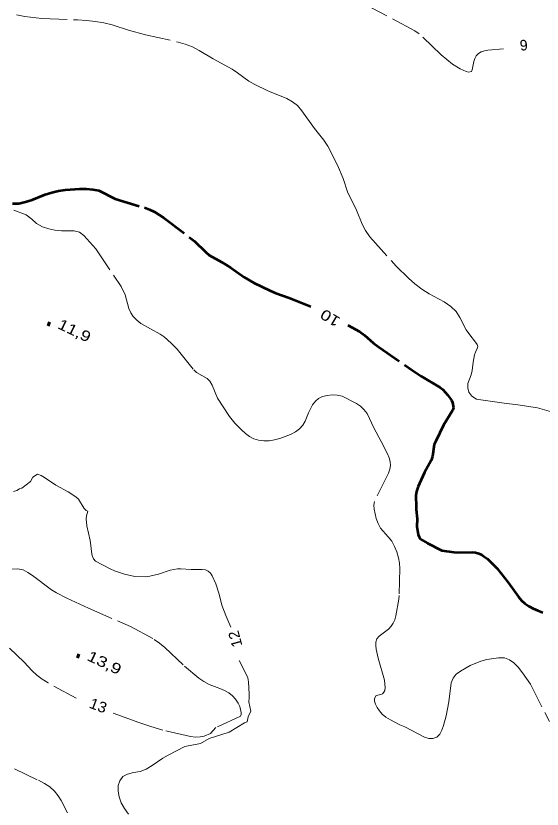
# Model space of a CAD drawing. Extents: x 355726 to 357533, y 5103782 to 5105258.
# Drawn here: x 356617.7 to 356692.4, y 5104170 to 5104282.7 of the extents above; entities that cross this region are included whole.
import ezdxf
from ezdxf.enums import TextEntityAlignment as Align

# ---------------------------------------------------------------- set-up
doc = ezdxf.new("R2010")
doc.units = 0
doc.header["$LTSCALE"] = 0.6
doc.linetypes.add('LONG_DASHED', pattern=[7.5, 6, -1.5])
for name, color, linetype, lineweight in [('1', 7, 'LONG_DASHED', 53), ('2', 7, 'LONG_DASHED', 13), ('3', 7, 'Continuous', 140)]:
    doc.layers.add(name, color=color, linetype=linetype, lineweight=lineweight)

msp = doc.modelspace()

# ---------------------------------------------------------------- linework, layer by layer
at = {"layer": '1'}
for points in [[(356617.23, 5104256.04), (356618.14, 5104256.07), (356619.1, 5104256.28), (356620.05, 5104256.59), (356621.87, 5104257.34), (356622.82, 5104257.63), (356623.78, 5104257.86), (356624.75, 5104258.01), (356626.76, 5104258.13), (356627.76, 5104258.11), (356628.66, 5104258.05), (356629.5, 5104257.88), (356631.8, 5104256.73), (356635.96, 5104255.47), (356636.71, 5104255.2), (356637.42, 5104254.86), (356638.74, 5104254.01), (356643.09, 5104250.7), (356644.67, 5104249.12), (356645.18, 5104248.69), (356646.95, 5104247.73), (356648.19, 5104246.98), (356650.12, 5104245.57), (356651.51, 5104244.8), (356653.76, 5104243.69), (356654.62, 5104243.32), (356656.53, 5104242.67), (356659.58, 5104241.42)], [(356664.84, 5104238.79), (356666.5, 5104237.88), (356667.22, 5104237.34), (356668.52, 5104236.2), (356669.19, 5104235.69), (356673.97, 5104232.38), (356675.27, 5104231.51), (356677.95, 5104229.93), (356678.33, 5104229.61), (356679.03, 5104228.86), (356679.56, 5104228.13), (356679.71, 5104227.79), (356679.84, 5104227.03), (356679.71, 5104226.66), (356678.45, 5104224.58), (356677.33, 5104222.3), (356677.12, 5104221.8), (356676.86, 5104220.13), (356676.67, 5104219.55), (356675.76, 5104217.82), (356675.01, 5104216.26), (356674.82, 5104215.84), (356674.6, 5104215.13), (356674.51, 5104214.51), (356674.58, 5104213.03), (356674.56, 5104212.57), (356674.7, 5104211.26), (356674.65, 5104210.15), (356674.86, 5104209.01), (356674.97, 5104208.68), (356675.17, 5104208.38), (356676.17, 5104207.8), (356678.2, 5104206.76), (356679.9, 5104206.51), (356680.43, 5104206.48), (356682.49, 5104206.51), (356682.98, 5104206.46), (356683.45, 5104206.34), (356683.86, 5104206.12), (356684.28, 5104205.88), (356684.71, 5104205.55), (356686.06, 5104204.19), (356687.64, 5104202.19), (356689.1, 5104200.16), (356689.52, 5104199.66), (356690.01, 5104199.24), (356690.57, 5104198.86), (356691.19, 5104198.53), (356691.84, 5104198.21), (356692.56, 5104197.94)]]:
    msp.add_lwpolyline(points, dxfattribs=at)
at = {"layer": '2'}
for points in [[(356686.94, 5104278), (356684.75, 5104277.84), (356684.27, 5104277.76), (356683.8, 5104277.59), (356683.4, 5104277.34), (356683.09, 5104277.04), (356682.88, 5104276.63), (356682.73, 5104276.23), (356682.53, 5104275.03), (356682.41, 5104274.8), (356682, 5104274.71), (356681.68, 5104274.8), (356680.81, 5104275.19), (356679.73, 5104275.82), (356678.12, 5104277.19), (356674.98, 5104280.15), (356674.36, 5104280.58), (356664.65, 5104285.73)], [(356617.82, 5104282.87), (356619, 5104282.62), (356621.38, 5104282.32), (356626.46, 5104282.13), (356627.75, 5104282.04), (356629, 5104281.9), (356630.22, 5104281.7), (356631.4, 5104281.42), (356633.72, 5104280.69), (356636.11, 5104280.01), (356640.75, 5104278.98), (356641.77, 5104278.68), (356642.78, 5104278.3), (356643.74, 5104277.8), (356645.72, 5104276.59), (356648.44, 5104275.12), (356649.21, 5104274.62), (356650.78, 5104273.44), (356651.63, 5104272.97), (356653.5, 5104272.07), (356656.19, 5104270.96), (356656.98, 5104270.51), (356657.7, 5104269.95), (356658.32, 5104269.23), (356660.14, 5104266.69), (356661.45, 5104265.07), (356662, 5104264.21), (356663.39, 5104261.48), (356664.17, 5104259.59), (356664.8, 5104257.69), (356666.08, 5104255.08), (356666.88, 5104253.13), (356667.37, 5104252.21), (356667.98, 5104251.3), (356671.72, 5104247.16), (356673.46, 5104245.45), (356674.39, 5104244.63), (356675.35, 5104243.9), (356676.41, 5104243.22), (356678.54, 5104242.07), (356679.49, 5104241.43), (356680.23, 5104240.69), (356680.75, 5104239.84), (356681.67, 5104238.09), (356682.16, 5104237.37), (356682.97, 5104236.37), (356683.2, 5104236), (356683.31, 5104235.75), (356683.23, 5104235.43), (356682.97, 5104234.91), (356682.85, 5104234.54), (356682.65, 5104233.53), (356682.5, 5104232.32), (356682.36, 5104231.69), (356681.91, 5104230.49), (356681.89, 5104229.88), (356682.06, 5104229.25), (356682.47, 5104228.66), (356683.14, 5104228.26), (356684.08, 5104228.09), (356687.06, 5104227.67), (356688.98, 5104227.47), (356691.81, 5104227.01), (356693.78, 5104226.46)], [(356617.44, 5104255.09), (356619.19, 5104254.42), (356619.96, 5104253.83), (356620.66, 5104253.21)], [(356620.66, 5104253.21), (356621.49, 5104252.75), (356622.38, 5104252.43), (356623.26, 5104252.24), (356624.18, 5104252.19), (356625.99, 5104252.19), (356626.74, 5104251.98), (356627.38, 5104251.49), (356629.06, 5104249.59), (356632.65, 5104244.28), (356633.25, 5104243.09), (356633.77, 5104241.15), (356634.02, 5104240.54), (356634.38, 5104239.98), (356634.87, 5104239.48), (356635.46, 5104239.01), (356638.2, 5104237.5), (356638.76, 5104237.09), (356639.75, 5104236.22), (356640.63, 5104235.34), (356642.99, 5104232.4), (356643.38, 5104232.04), (356644.87, 5104231.21), (356645.26, 5104230.8), (356645.57, 5104230.23), (356646.36, 5104228.38), (356648.03, 5104225.79), (356648.81, 5104224.83), (356649.76, 5104223.88), (356650.3, 5104223.38), (356650.88, 5104222.95), (356651.5, 5104222.62), (356652.19, 5104222.42), (356652.91, 5104222.32), (356653.66, 5104222.34), (356654.44, 5104222.48), (356655.21, 5104222.69), (356656.72, 5104223.23), (356657.42, 5104223.59), (356658, 5104224.05), (356658.46, 5104224.55), (356658.8, 5104225.12), (356659.27, 5104226.33), (356659.84, 5104227.46), (356660.24, 5104227.95), (356660.71, 5104228.34), (356661.28, 5104228.63), (356661.93, 5104228.79), (356662.63, 5104228.86), (356663.33, 5104228.84), (356664.06, 5104228.69), (356666.07, 5104227.65), (356666.65, 5104227.26), (356667.15, 5104226.8), (356667.58, 5104226.22), (356668.56, 5104224.16), (356669.6, 5104222.26), (356670.48, 5104220.49), (356670.72, 5104219.94), (356670.86, 5104219.38), (356670.89, 5104218.84), (356670.81, 5104218.3), (356670.63, 5104217.75), (356668.65, 5104213.73), (356668.57, 5104213.2), (356668.6, 5104212.63), (356668.86, 5104211.3), (356669.14, 5104210.61), (356669.5, 5104209.94), (356670.58, 5104208.72), (356671.08, 5104208.07), (356671.49, 5104207.34), (356671.81, 5104206.55), (356672.07, 5104205.73), (356672.2, 5104204.94), (356672.23, 5104204.18), (356672.14, 5104200.38), (356672.1, 5104199.84), (356671.68, 5104197.48), (356671.51, 5104196.93), (356671.28, 5104196.45), (356670.99, 5104195.99), (356670.62, 5104195.59), (356669.31, 5104194.61), (356668.98, 5104194.2), (356668.82, 5104193.75), (356668.81, 5104193.28), (356668.88, 5104192.74), (356669.18, 5104191.48), (356670.07, 5104188.34), (356670.16, 5104187.3), (356670.12, 5104186.88), (356669.98, 5104186.61), (356669.79, 5104186.4), (356669.52, 5104186.29), (356668.9, 5104186.15), (356668.62, 5104185.71), (356668.66, 5104185.34), (356668.79, 5104184.92), (356669.02, 5104184.45), (356669.34, 5104183.98)], [(356617.36, 5104215.15), (356617.84, 5104215.3), (356618.21, 5104215.51), (356618.54, 5104215.61), (356619.8, 5104216.54), (356620.1, 5104217.17), (356620.78, 5104217.58), (356621.29, 5104217.41), (356621.79, 5104217.12), (356623.4, 5104216.03), (356625.14, 5104215.09), (356626.23, 5104214.4), (356626.6, 5104214.03), (356627.41, 5104212.73), (356627.7, 5104212.46), (356627.92, 5104212.34), (356627.75, 5104211.69)], [(356627.75, 5104211.69), (356627.7, 5104211.26), (356627.77, 5104210.28), (356628.27, 5104208.16), (356628.42, 5104207.09), (356628.44, 5104206.55), (356628.55, 5104206.05), (356628.73, 5104205.59), (356629.02, 5104205.23), (356631.11, 5104204.13), (356631.74, 5104203.88), (356633.14, 5104203.38), (356634.63, 5104203.05), (356636.08, 5104203.01), (356636.74, 5104203.09), (356637.95, 5104203.41), (356639.62, 5104203.95), (356640.66, 5104204.15), (356641.16, 5104204.17), (356642.6, 5104204.07), (356644.18, 5104204.08), (356644.66, 5104204.01), (356645.04, 5104203.84), (356645.36, 5104203.54), (356645.6, 5104203.15), (356646.09, 5104202.04), (356646.56, 5104200.54), (356646.96, 5104198.99), (356647.51, 5104197.51), (356648.22, 5104195.86)], [(356617.21, 5104204.12), (356618, 5104204.15), (356618.73, 5104203.99), (356619.4, 5104203.65), (356620.07, 5104203.2), (356622.77, 5104201.19), (356623.49, 5104200.75), (356624.94, 5104199.98), (356628.03, 5104198.55), (356634.01, 5104195.96), (356637.36, 5104194.13), (356638.13, 5104193.58), (356638.87, 5104192.97), (356641.66, 5104190.34), (356643.7, 5104188.63), (356644.41, 5104188.13), (356645.15, 5104187.71), (356646.69, 5104187.16), (356647.36, 5104186.86), (356647.94, 5104186.53), (356648.47, 5104186.13), (356648.9, 5104185.63), (356649.27, 5104185.09), (356649.5, 5104184.58), (356649.7, 5104183.76), (356649.71, 5104183.46), (356649.6, 5104183.2), (356646.13, 5104181.62), (356645.37, 5104180.76), (356644.45, 5104180.38), (356643.88, 5104180.28), (356643.22, 5104180.25), (356642.5, 5104180.33), (356638.6, 5104181.25), (356636.88, 5104181.76), (356635.05, 5104182.38), (356633.22, 5104183.01), (356631.53, 5104183.67)], [(356626.28, 5104185.8), (356622.28, 5104187.95), (356621.46, 5104188.48), (356620.69, 5104189.05), (356620.01, 5104189.67), (356618.89, 5104190.9), (356616.8, 5104192.9)], [(356649.41, 5104191.11), (356650.42, 5104189.19), (356650.64, 5104188.66), (356650.73, 5104188.09), (356650.84, 5104186.37), (356650.85, 5104185.82), (356650.79, 5104185.26), (356651.06, 5104183.91), (356650.68, 5104183.12), (356650.54, 5104182.44), (356650.16, 5104182.28), (356648.01, 5104180.97), (356645.18, 5104180.04), (356643.93, 5104179.32), (356641.72, 5104178.9), (356639.32, 5104177.7), (356638.59, 5104177.26), (356637.06, 5104176.2), (356636.24, 5104175.69), (356635.35, 5104175.38), (356634.44, 5104175.22), (356633.58, 5104175), (356632.89, 5104174.63), (356632.46, 5104174.04), (356632.25, 5104173.36), (356632.24, 5104172.55), (356632.39, 5104171.74), (356632.69, 5104170.92), (356633.15, 5104170.11), (356633.7, 5104169.32)], [(356669.34, 5104183.98), (356669.75, 5104183.51), (356670.27, 5104183.07), (356670.89, 5104182.7), (356672.25, 5104182.01), (356672.96, 5104181.71), (356675.75, 5104180.26), (356676.35, 5104180.07), (356676.93, 5104180.05), (356677.47, 5104180.25), (356677.9, 5104180.67), (356678.22, 5104181.24), (356678.46, 5104181.88), (356678.82, 5104183.29), (356679.2, 5104185.28), (356679.54, 5104187.97), (356679.8, 5104188.61), (356680.22, 5104189.18), (356680.84, 5104189.63), (356682.23, 5104190.44), (356683.75, 5104191.05), (356684.57, 5104191.26), (356686.27, 5104191.51), (356687.1, 5104191.49), (356687.8, 5104191.24), (356688.43, 5104190.79), (356689.04, 5104190.16), (356689.66, 5104189.4), (356690.79, 5104187.75), (356693.48, 5104182.47)], [(356617.51, 5104175.76), (356620.92, 5104174.12), (356621.78, 5104173.66), (356622.56, 5104173.17), (356623.19, 5104172.59), (356623.72, 5104171.91)], [(356623.72, 5104171.91), (356624.15, 5104171.22), (356625.05, 5104169.49)]]:
    msp.add_lwpolyline(points, dxfattribs=at)
at = {"layer": '3'}
for p, q in [((356622.22, 5104239.01), (356622.58, 5104238.84)), ((356626.39, 5104191.86), (356626.75, 5104191.69))]:
    msp.add_line(p, q, dxfattribs=at)

# ---------------------------------------------------------------- texts
at = {"layer": '1', "width": 1.25}
msp.add_text('10', height=1.5, rotation=149.436, dxfattribs=at).set_placement((356662.73, 5104240.43), align=Align.CENTER)
at = {"layer": '2'}
msp.add_text('9', height=1.5, rotation=5.916, dxfattribs=at).set_placement((356689.91, 5104277.8), align=Align.CENTER)
for s, rotation, width, p in [('12', 105.317, 1.05, (356649.59, 5104194.38)), ('13', 339.361, 1.1, (356629.15, 5104184.03))]:
    msp.add_text(s, height=1.5, rotation=rotation, dxfattribs=dict(at, width=width)).set_placement(p, align=Align.CENTER)
at = {"layer": '3'}
for s, width, p in [('11,9   ', 1.25, (356623.51, 5104238.38)), ('13,9   ', 1.3, (356627.68, 5104191.24))]:
    msp.add_text(s, height=1.5, rotation=334.423, dxfattribs=dict(at, width=width)).set_placement(p)

doc.saveas('drawing.dxf')
